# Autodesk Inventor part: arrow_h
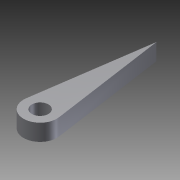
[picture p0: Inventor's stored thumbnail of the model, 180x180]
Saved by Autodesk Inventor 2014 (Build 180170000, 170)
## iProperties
Created: 2013-08
Part Number: arrow_h
Material: Типовые
Document SubType Name: Modeling
Designer: ed
Density: 1 g/cm^3
Appearance: По умолчанию
Author: ed
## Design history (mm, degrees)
sketch "Эскиз1"
  geometry: L1 (-9.897, 1.429)-(0, 70); L2 (0, 70)-(9.897, 1.429); L3 (0, 0)-(0, 53.426); C1 r 5 at (0, 0); A1 r 10 centre (0, 0) between (-9.897, 1.429) and (9.897, 1.429); 1 further point
  constraints: 6 end point, 2 centre point, 2 coincident, 2 point on circle, 2 tangent, 1 vertical, 1 other
  dimensions: "d0" = 20 diameter of A1; "d1" = 10 diameter of C1; "d2" = 70 distance of L1.end point (0, 0)
extrude "Выдавливание1" new body sketch "Эскиз1" distance "d3" = 10; taper "d4" = 0 deg
node "Твердое тело1"
